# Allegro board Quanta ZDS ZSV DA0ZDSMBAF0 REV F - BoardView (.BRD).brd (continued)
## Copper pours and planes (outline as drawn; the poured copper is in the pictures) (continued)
VCCSA on IN1 (solid shape): 116.75,46.95 116.75,46.84 116.75,46.84 116.75,46.35 116.48,46.08 116.48,45.81 116.69,45.6 116.69,45.23 116.46,44.99 116.46,44.69 116.49,44.66 116.68,44.47 116.69,44.45 116.7,44.43 116.7,44.11 116.49,43.91 116.49,43.56 116.69,43.36 116.7,43.34 116.7,43.32 116.7,42.99 116.48,42.76 116.48,42.42 116.7,42.2 116.7,41.9 116.46,41.65 116.46,41.32 116.49,41.3 116.7,41.09 116.7,40.76 116.46,40.52 116.46,40.22 116.68,40 116.69,39.98 116.7,39.96 116.7,39.64 116.46,39.41 116.46,39.13 116.38,39.05 116.12,39.05 116.06,39.11 116.06,42.26 116.09,42.29 116.09,46.14 116.43,46.48 116.46,46.5 116.5,46.57 116.52,46.65 116.5,46.74 116.5,46.75 116.5,46.92 116.56,46.98 116.71,46.98
VCCSA on IN1 (solid shape): outline of 291 points within 136.75,46.1 153.19,56.74
VCCSA on GND1 (solid shape): 116.43,46.08 116.48,46.06 116.52,46.03 116.52,46 116.53,45.87 116.63,45.78 116.66,45.76 116.66,45.76 116.66,45.03 116.66,45.03 116.63,45.02 116.51,44.84 116.63,44.66 116.64,44.65 116.66,44.63 116.66,43.92 116.66,43.91 116.63,43.9 116.51,43.72 116.63,43.54 116.64,43.54 116.66,43.51 116.66,42.87 116.66,42.85 116.65,42.84 116.47,42.66 116.47,42.49 116.69,42.27 116.69,41.68 116.51,41.5 116.65,41.3 116.68,41.28 116.69,41.25 116.69,40.6 116.68,40.57 116.65,40.55 116.51,40.37 116.65,40.18 116.67,40.18 116.69,40.15 116.69,39.71 116.58,39.61 116.2,39.61 116.1,39.71 116.1,46 116.18,46.08
VCCSA on IN2 (solid shape): 153.79,56.05 153.79,48.57 153.47,48.25 149.79,48.25 147.66,50.38 147.62,50.38 147.62,50.46 147.65,50.48 149.36,53.25 147.82,56.13 147.77,56.24 147.87,56.32 153.53,56.32
VCCSA on IN2 (solid shape): 116.56,45.96 116.56,44.44 116.64,44.36 116.64,44.27 116.55,44.18 116.55,42.2 116.63,42.12 116.63,42.05 116.59,42.01 116.59,41.03 116.64,40.98 116.64,40.91 116.59,40.86 116.59,39.87 116.64,39.82 116.64,39.8 116.53,39.69 116.42,39.69 116.39,39.66 115.86,39.66 115.78,39.73 115.78,39.97 115.78,39.98 115.81,40.09 115.78,40.21 115.78,40.22 115.78,40.48 115.83,40.64 115.78,40.8 115.78,41.05 115.79,41.06 115.83,41.2 115.79,41.35 115.78,41.36 115.78,41.66 115.79,41.67 115.83,41.81 115.79,41.95 115.78,41.97 115.78,45.77 115.79,45.8 115.79,46.09 115.88,46.18 116.34,46.18
VCCSA on IN2 (solid shape): 142.83,55.65 142.83,51.1 142.46,50.73 141.91,50.73 140.49,52.15 140.47,52.26 140.57,52.32 141.33,54.08 139.57,53.32 139.51,53.22 139.4,53.24 136.63,56.01 136.6,56.13 136.7,56.19 142.29,56.19
VCCSA on SVCC (solid shape): 118.87,54.61 118.87,51.67 118.94,51.67 118.98,51.66 118.99,51.62 118.99,51.48 116.76,49.24 116.76,48.25 116.78,48.22 116.78,42.52 116.79,42.52 116.79,38.71 116.77,38.68 116.74,38.66 116.08,38.66 115.8,38.94 115.8,39.37 115.86,39.54 115.8,39.71 115.8,40.01 115.81,40.09 115.8,40.17 115.8,40.51 115.8,40.52 115.83,40.64 115.8,40.77 115.8,40.78 115.8,41.08 115.8,41.09 115.83,41.2 115.8,41.32 115.8,41.33 115.8,41.69 115.8,41.7 115.83,41.81 115.8,41.93 115.8,41.94 115.8,42.12 115.79,42.12 115.79,42.3 114.88,43.21 114.75,43.21 114.52,43.44 114.52,47.66 114.52,48.42 114.54,48.43 114.61,48.62 114.54,48.81 114.53,48.83 114.52,48.85 114.52,55.1 114.78,55.35 118.13,55.35
VCCSA on IN3 (solid shape): 116.81,46.05 116.81,39.91 116.74,39.83 116.28,39.83 116.17,39.94 116.17,43.22 116.1,43.29 116.1,45.8 116.45,46.15 116.71,46.15
VCCSA on IN3 (solid shape): 153.94,56.18 153.94,51.9 153.7,51.67 149.28,51.67 149.03,51.92 149.15,54.5 147.35,56.37 147.23,56.41 147.17,56.52 147.25,56.61 153.52,56.61
VCCSA on IN3 (solid shape): outline of 131 points within 136.82,51.7 145.03,56.61
VCCSA on GND2 (solid shape): 116.76,45.98 116.76,39.99 116.66,39.89 116.3,39.89 116.15,40.04 116.15,40.83 116.15,40.87 116.15,40.91 116.15,42.94 116.16,42.96 116.17,42.98 116.26,43.16 116.17,43.34 116.16,43.35 116.15,43.37 116.15,45.28 116.16,45.29 116.18,45.39 116.16,45.49 116.15,45.5 116.15,45.79 116.45,46.08 116.65,46.08
VCCSA on IN4 (solid shape): outline of 141 points within 115.32,40.19 117.7,54.3
VCCSA_DDR on BOTTOM (solid shape): 115.08,51.43 115.08,50.88 115.44,50.53 115.44,49.26 114.94,48.76 114.67,48.76 114.66,48.78 114.39,48.78 114.12,49.05 114.12,51.47 114.17,51.52 114.99,51.52
VCCSA_DDR on IN3 (solid shape): 115.69,49.51 115.69,48.75 115.56,48.62 114.93,48.62 114.8,48.75 114.8,49.64 114.93,49.77 115.44,49.77
VDDQ_SRC on TOP (solid shape): 79.19,59.71 79.19,54.75 79.37,54.57 79.37,54.08 79.27,54.08 79.27,52.6 79.09,52.42 78.07,52.42 77.92,52.57 77.92,54.12 77.31,54.73 75.74,54.73 75.33,55.13 75.33,59.35 75.79,59.81 79.09,59.81
VDDQ_SRC on BOTTOM (solid shape): 79.12,55.31 79.12,54.85 79,54.74 78.42,54.74 78.36,54.68 77.72,54.68 77.54,54.85 77.54,55.21 77.77,55.44 78.99,55.44
VDDQ_VIN on TOP (solid shape): 71.8,57.17 71.8,55.17 72.03,54.94 72.03,54.93 72.03,53.79 72.03,53.63 72.1,53.56 73.06,53.56 73.06,53.57 73.06,54.26 73.12,54.32 73.6,54.32 73.65,54.27 73.65,51.91 73.53,51.79 71.76,51.79 71.01,52.54 70.66,52.54 70.4,52.8 70.4,56.45 69.95,56.91 69.95,57.14 70.07,57.27 71.7,57.27
VINLDO1 on TOP (solid shape): 79.12,46.62 79.12,45.74 78.91,45.53 75.13,45.53 74.85,45.25 73.37,45.25 73.09,45.53 71.98,45.53 71.9,45.61 71.9,45.79 72,45.89 74.26,45.89 75.08,46.7 79.04,46.7
VINVR2 on TOP (solid shape): 70.15,42.81 70.15,42.09 70.14,42.07 70.12,42.04 70.11,42 70.11,41.15 70.11,41.15 70.11,40.86 70.12,40.81 70.14,40.75 70.15,40.74 70.15,40.66 70.27,40.53 70.63,40.53 71.14,40.02 71.17,40.02 72.28,38.9 72.28,38.55 72.18,38.45 70,38.45 69.86,38.59 69.86,39.42 69.39,39.89 69.39,40.86 69.78,41.25 69.78,41.73 69.87,41.81 69.87,42.79 69.94,42.87 70.1,42.87
13_CCD_PW on BOTTOM (solid shape): 4.11,18.85 4.11,17.89 4.23,17.77 6.38,17.77 6.48,17.67 6.48,16.81 6.34,16.67 2.79,16.67 2.56,16.9 2.56,19.12 2.64,19.2 3.76,19.2
8350_GND on IN3 (solid shape): 162.93,13.44 162.93,13.22 162.78,13.06 162.53,13.06 162.38,12.91 162.38,12.71 162.27,12.61 161.94,12.61 161.87,12.68 161.87,13.14 162.4,13.67 162.71,13.67
+1.8U on TOP (solid shape): 89.05,59.63 89.05,58.16 88.84,57.95 88.46,57.95 88.33,58.08 86.51,58.08 86.3,58.28 86.3,59.63 86.48,59.81 88.87,59.81
+1.8U on BOTTOM (solid shape): 131.74,17.54 131.74,17.53 131.85,17.43 132.89,17.43 133.09,17.23 133.09,14.87 132.94,14.72 129.71,14.72 129.15,15.28 129.15,16.33 129.24,16.56 129.15,16.79 129.15,17.13 129.24,17.36 129.15,17.59 129.15,17.85 129.23,17.92 131.36,17.92
+1.8U on BOTTOM (solid shape): 179.04,11.39 179.04,10.44 179.04,10.44 179.04,9.97 178.5,9.43 177.79,9.43 177.37,9.02 177.36,9.02 177.36,8.04 177.31,7.98 177.11,7.98 177.07,8 177.06,8.03 177.06,9.02 176.86,9.02 176.86,8.03 176.85,8 176.81,7.98 176.65,7.98 176.56,8.08 176.56,9.02 176.56,9.16 176.78,9.38 176.78,10.01 177.03,10.27 177.74,10.27 177.79,10.32 177.79,11.52 177.92,11.64 178.79,11.64
+1.8U on BOTTOM (solid shape): 147.95,14.49 148.14,14.43 148.34,14.49 148.74,14.49 148.93,14.43 149.12,14.49 149.55,14.49 149.74,14.43 149.94,14.49 150.34,14.49 150.41,14.46 150.43,14.44 150.44,14.41 150.44,11 150.22,10.78 148.91,10.78 148.69,11.01 148.69,12.22 148.58,12.33 147.67,12.33 147.52,12.48 147.52,14.34 147.67,14.49
+1.8U on BOTTOM (solid shape): 101.16,17.77 101.16,17.58 101.07,17.35 101.16,17.12 101.16,16.79 101.07,16.56 101.16,16.33 101.16,15.98 101.07,15.75 101.16,15.52 101.16,15.19 101.09,15.08 101.07,14.94 101.06,14.92 100.81,14.67 97.51,14.67 97.23,14.95 97.23,17.64 97.45,17.87 101.06,17.87
+1.8U on BOTTOM (solid shape): 155.77,43.11 155.77,42.12 155.67,42.02 153.08,42.02 152.42,42.68 151.89,42.68 151.84,42.69 151.79,42.68 150.78,42.68 150.74,42.68 150.39,42.32 150.39,42.15 150.26,42.02 149.29,42.02 149.27,42.03 149.25,42.04 148.96,42.21 148.68,42.04 148.66,42.03 148.63,42.02 148.51,42.02 148.49,42.03 148.47,42.05 148.18,42.22 147.88,42.05 147.87,42.03 147.84,42.02 147.62,42.02 147.49,42.15 147.49,43.19 147.59,43.29 155.59,43.29
+1.8U on BOTTOM (solid shape): outline of 223 points within 111.37,12.08 118.94,18.02
+1.8U on BOTTOM (solid shape): outline of 272 points within 147.16,24.72 155.65,32.29
+1.8U on IN3 (solid shape): 89.51,58.79 89.62,58.42 90,58.42 90.54,58.42 90.63,58.33 90.63,55.52 93.77,52.38 93.77,44.67 93.26,44.16 92.45,44.16 91.99,44.62 91.99,51.83 88.9,54.93 88.9,56.36 88.91,56.56 88.88,56.76 88.85,56.97 88.79,57.17 88.79,57.43 88.52,57.7 88.5,57.7 88.36,57.87 88.2,58.02 87.12,58.02 86.89,58.26 86.89,58.61 87.07,58.79
+1.8U on IN3 (solid shape): outline of 14479 points within 90.29,11.94 156.36,43.05
+1.8U on IN4 (solid shape): outline of 600 points within 85.99,24.62 95.24,45.61
+1.8U on IN4 (solid shape): outline of 1010 points within 153,10.45 179.27,18.86
+1.8U_S2 on TOP (solid shape): 86.02,59.5 86.02,58.33 85.89,58.19 85.66,58.19 84.86,57.39 83.82,57.39 83.79,57.41 83.77,57.44 83.77,58.12 83.57,58.12 83.57,57.44 83.56,57.41 83.52,57.39 83.46,57.39 83.4,57.46 83.4,58.34 84.07,59.01 84.07,59.2 84.2,59.32 84.7,59.32 85.03,59.65 85.87,59.65
+BAT_DIS on BOTTOM (solid shape): 82.52,21.1 82.52,18.43 81.68,17.6 81.68,16.72 81.71,16.7 81.71,15.31 81.49,15.09 80.58,15.09 80.46,15.2 80.46,15.99 80.23,16.22 78.56,16.22 78.46,16.32 78.46,18.13 77.54,19.04 77.49,19.27 77.31,19.43 77.31,21.2 77.52,21.4 82.21,21.4
+BATCHG on BOTTOM (solid shape): 86.41,18.76 86.41,13.93 86.15,13.68 84.61,13.68 84.61,13.73 83.06,13.73 82.87,13.91 82.87,15.84 83.15,16.12 83.28,16.12 83.33,16.17 83.33,16.65 83.36,16.68 83.36,18.71 83.59,18.94 86.23,18.94
+MUX_PWR on BOTTOM (solid shape): 240.15,22.59 240.15,21.44 240.91,20.68 240.91,18.9 240.4,18.4 239.64,18.4 239.39,18.65 239.39,22.33 239.77,22.71 240.02,22.71
+POA_PWR on BOTTOM (solid shape): 171.64,14.6 171.64,14.35 171.14,13.86 171.14,13.27 171.29,13.11 172.03,13.11 172.13,13.01 172.13,12.45 172,12.33 170.94,12.33 170.68,12.07 170.68,11.92 170.66,11.89 170.28,11.89 170.17,12 170.17,12.28 170.33,12.43 170.5,12.43 170.71,12.63 170.71,14.64 170.76,14.69 171.55,14.69
+PRWSRC on BOTTOM (solid shape): 88.29,23.81 88.29,22.95 88.77,22.47 88.77,21.55 89.05,21.28 89.73,21.28 89.82,21.19 89.82,19.54 89.15,18.86 86.89,18.86 86.61,19.14 86.61,19.83 86.69,19.91 86.69,20.59 86.68,20.59 86.68,21.13 86.19,21.62 86.19,23.77 86.47,24.04 88.05,24.04
+SMDDR_VREF_CA on BOTTOM (solid shape): 155.6,24.58 155.6,20.92 155.42,20.74 154.58,20.74 154.45,20.87 154.45,24.63 154.48,24.65 155.52,24.65
+SMDDR_VREF_DQA on BOTTOM (solid shape): 140.05,20.72 140.05,19.19 139.92,19.07 138.6,19.07 138.57,19.11 138.48,19.2 138.48,20.79 138.55,20.87 139.9,20.87
+SMDDR_VREF_DQA on BOTTOM (solid shape): 140.43,40.07 140.43,35.96 140.28,35.8 138.78,35.8 138.69,35.89 138.68,35.92 138.68,37.43 138.7,37.44 138.68,37.45 138.68,40.12 138.75,40.2 140.3,40.2
+SMDDR_VREF_DQA on IN3 (solid shape): 143.6,37.12 143.6,36.44 143.57,36.41 143.55,36.41 139.77,36.41 139.59,36.58 139.59,38.62 139.69,38.72 142.01,38.72
+SMDDR_VREF_DQA on IN3 (solid shape): 143.81,20.15 143.81,19.06 143.68,18.93 143.38,18.93 142.94,19.37 142.93,19.38 142.74,19.59 142.46,19.54 139.92,19.54 139.9,19.51 139.57,19.51 139.39,19.69 139.39,20.58 139.64,20.84 143.12,20.84
+SMDDR_VREF_DQB on BOTTOM (solid shape): 107.69,26.84 107.69,24.77 106.8,23.88 106.24,23.88 104.92,25.2 104.92,26.74 105.1,26.91 107.61,26.91
+SMDDR_VREF_DQB on BOTTOM (solid shape): 123.85,26.96 123.9,26.91 123.9,26.04 124.3,25.64 124.3,24.14 124.1,23.93 123.21,23.93 123.03,24.11 123.03,25.47 122.73,25.77 120.9,25.77 120.77,25.9 120.77,26.89 120.85,26.96 123.44,26.96
+SMDDR_VTERM on BOTTOM (solid shape): 138.35,39.05 138.35,38.39 138.22,38.26 136.98,38.26 136.85,38.39 136.85,38.83 137.14,39.12 138.27,39.12
+SMDDR_VTERM on BOTTOM (solid shape): 121.36,27.69 121.36,27.34 121.28,27.26 120.59,27.26 120.21,26.88 120.21,26.02 120.14,25.94 119.37,25.94 119.25,26.07 119.25,27.66 119.32,27.73 121.32,27.73
+SMDDR_VTERM on IN3 (solid shape): 121.08,26.14 121.08,25.84 121,25.76 119.25,25.76 119.17,25.84 119.17,26.19 119.27,26.3 120.92,26.3
+SMDDR_VTERM on IN3 (solid shape): 137.74,38.51 137.74,37.19 137.61,37.07 136.72,37.07 136.6,37.19 136.6,37.85 137.41,38.67 137.59,38.67
+SMDDR_VTERM on IN4 (solid shape): 120.95,26.19 120.95,25.86 120.87,25.79 118.74,25.79 118.66,25.86 118.66,26.25 118.71,26.3 120.85,26.3
+VA on TOP (solid shape): outline of 909 points within 201.67,2.52 215,22.08
+VA on BOTTOM (solid shape): 96.9,17.97 96.9,9.6 97.62,8.88 98.37,8.88 98.57,8.68 98.57,6.43 98.16,6.03 98.16,5.15 97.83,4.82 92.89,4.82 92.48,5.23 92.48,13.17 93.67,14.37 93.67,17.8 94.43,18.56 96.31,18.56
+VA on BOTTOM (solid shape): 210.18,21.44 211.45,21.44 211.7,21.19 211.7,20.3 212.21,19.79 212.21,16.66 212.06,16.52 212.06,15.7 212.21,15.56 212.21,13.95 212.46,13.7 212.46,12.55 212.34,12.43 208.78,12.43 208.65,12.55 208.65,13.32 208.53,13.44 206.5,13.44 206.11,13.82 206.11,22.08 206.37,22.33 209.29,22.33
+VA on IN4 (solid shape): outline of 6127 points within 95.52,2.49 206.5,10
+VAD on BOTTOM (solid shape): 71.65,17.29 71.65,15.97 71.34,15.66 70.71,15.66 70.06,16.31 70.06,16.46 70.05,16.47 70.05,17.31 70.24,17.5 71.43,17.5
+VAD on BOTTOM (solid shape): 94.15,22.42 94.15,18.61 93.42,17.87 93.42,14.49 93.14,14.21 88.92,14.21 88.51,14.62 88.51,18.4 88.64,18.53 89.48,18.53 90.11,19.17 90.11,22.21 90.57,22.67 90.57,23.54 90.83,23.79 92.78,23.79
+WL_VDD on TOP (solid shape): 40.93,57.46 40.93,55.44 40.85,55.36 39.65,55.36 39.55,55.47 39.55,57.48 39.65,57.59 40.8,57.59
+WL_VDD on TOP (solid shape): 194.71,39.81 194.71,35.49 194.41,35.19 190.7,35.19 190.65,35.24 190.65,36.1 191.15,36.61 191.15,38.59 192.58,40.01 194.51,40.01
+WL_VDD on TOP (solid shape): 199.55,34.46 199.89,34.25 200.23,34.44 200.44,34.44 200.88,34 202.53,34 202.64,33.9 202.64,33.7 201.12,33.7 201.12,33.5 202.61,33.5 202.64,33.47 202.64,33.24 202.59,33.19 198.37,33.19 198.04,32.85 197.49,32.85 197.29,33.05 197.29,33.82 197.93,34.46
+WL_VDD on TOP (solid shape): outline of 865 points within 94.25,48.15 202.64,59.97
+WL_VDD on BOTTOM (solid shape): outline of 775 points within 39.24,46.84 69.21,59.8
+WL_VDD on SVCC (solid shape): outline of 82 points within 65.65,53.19 99.43,59.97
+WL_VDD on SVCC (solid shape): outline of 153 points within 193.92,32.75 203.38,53.07
ADOGND on TOP (solid shape): outline of 1155 points within 236.69,2.04 266.07,14.03
ADOGND on BOTTOM (solid shape): 257.12,13.76 257.12,12.03 256.94,11.85 253.36,11.85 253.08,12.13 253.08,13.86 253.21,13.99 256.89,13.99
ADOGND on BOTTOM (solid shape): 241.29,4.84 241.29,4.49 241.19,4.38 238.88,4.38 238.81,4.46 238.81,4.85 238.84,4.89 239.48,4.89 239.56,4.97 241.17,4.97
ADOGND on BOTTOM (solid shape): 268.83,11.73 268.85,11.62 268.76,11.56 262.94,11.56 262.94,3.44 263.88,3.44 263.88,2.99 261.93,2.99 261.93,12.43 268.14,12.43
ADOGND on IN1 (solid shape): outline of 1062 points within 236.69,2.04 262.94,14.03
ADOGND on GND1 (solid shape): outline of 1125 points within 236.62,1.94 269.53,14.04
ADOGND on SGND (solid shape): 258.29,12.49 261.62,12.49 262.87,13.74 267.45,13.74 268.71,12.49 274.74,12.49 274.78,12.47 274.79,12.44 274.79,11.61 274.78,11.57 274.74,11.56 262.94,11.56 262.94,3.44 274.74,3.44 274.78,3.43 274.79,3.39 274.79,2.66 274.78,2.62 274.74,2.61 272.35,2.61 270.69,1.51 269.72,1.51 268.8,2.42 266.06,2.42 265.57,1.94 237.41,1.94 236.62,2.73 236.62,7.02 236.8,7.2 237.69,7.2 237.79,7.1 237.79,5.58 238.4,4.97 240.79,4.97 240.96,5.14 240.96,7.05 241.22,7.31 243.84,7.31 244.12,7.58 245.31,7.58 245.36,7.53 245.36,6.67 245.28,6.59 244.32,6.59 244.09,6.37 244.09,5.12 243.58,4.61 243.58,4.44 243.58,4.42 243.56,4.4 243.28,4.18 242.94,4.18 242.62,3.85 242.62,3.24 243.02,2.83 244.32,2.83 244.65,2.5 246.5,2.5 246.86,2.86 246.86,5.83 246.91,5.88 250.24,5.88 250.54,6.19 250.54,10.88 250.82,11.16 250.82,13.51 250.97,13.68 250.97,13.91 251.1,14.04 256.74,14.04
ADOGND on SVCC (solid shape): 258.29,12.49 261.37,12.49 261.62,12.49 262.87,13.74 267.46,13.74 267.89,13.31 267.89,13.19 267.78,13.08 264.42,13.08 264.3,13.08 263.3,13.07 262.85,12.97 262.56,12.86 262.29,12.7 261.99,12.44 261.93,12.4 261.71,12.11 261.58,11.85 261.47,11.54 261.42,11.16 261.42,2.57 260.88,2.03 237.32,2.03 236.62,2.73 236.62,7.02 236.8,7.2 237.69,7.2 237.79,7.1 237.79,5.58 238.4,4.97 240.79,4.97 240.96,5.14 240.96,7.05 241.22,7.31 243.84,7.31 244.12,7.58 245.31,7.58 245.36,7.53 245.36,6.67 245.28,6.59 244.32,6.59 244.09,6.37 244.09,5.12 243.58,4.61 243.58,4.44 243.58,4.42 243.56,4.4 243.28,4.18 242.94,4.18 242.62,3.85 242.62,3.24 243.02,2.83 244.32,2.83 244.65,2.5 246.5,2.5 246.86,2.86 246.86,5.83 246.91,5.88 250.24,5.88 250.54,6.19 250.54,10.88 250.82,11.16 250.82,13.51 250.97,13.68 250.97,13.91 251.1,14.04 256.74,14.04
ADOGND on GND2 (solid shape): outline of 1125 points within 236.62,1.94 269.53,14.04
ADOGND on IN4 (solid shape): outline of 1098 points within 236.69,2.04 262.92,14.03
BATDIS_G on BOTTOM (solid shape): 90.42,23.92 90.42,22.95 89.96,22.49 89.96,21.73 89.68,21.45 89.1,21.45 89.05,21.5 89.05,22.34 88.56,22.82 88.56,24.04 88.59,24.07 90.27,24.07
BATT+ on BOTTOM (solid shape): 87.68,12.29 87.68,9.86 87.44,9.63 81.84,9.63 81.69,9.77 81.69,12.62 81.89,12.82 82.7,12.82 83.28,13.4 86.57,13.4
BQB_1 on BOTTOM (solid shape): 72.69,22.65 72.69,21.33 72.56,21.2 72.05,21.2 71.83,21.43 71.83,22.22 71.84,22.22 71.84,22.69 72.03,22.88 72.46,22.88
BQBATDRV on BOTTOM (solid shape): 82.09,14.94 82.09,14.59 81.63,14.14 80.67,14.14 80.46,14.34 80.46,14.67 80.74,14.95 81.5,14.95 81.55,14.99 82.04,14.99
BQHIDRV on BOTTOM (solid shape): 77.06,20.26 77.06,19.51 77.36,19.21 77.36,18.96 77.29,18.88 76.83,18.88 76.55,19.16 76.55,19.83 76.37,20.01 76.25,20.01 75.99,20.26 75.99,20.64 76.04,20.69 76.63,20.69
BQLODRV on BOTTOM (solid shape): 70.33,24.87 70.33,24.14 70.07,23.88 70.07,23.61 69.54,23.08 69.34,23.08 69.24,23.18 69.24,23.28 69.36,23.41 69.36,24.85 69.51,25 70.2,25
BQPHASE on BOTTOM (solid shape): 71.61,21.8 71.61,21.01 71.47,20.87 70.4,20.87 70.15,21.12 69.77,21.12 69.74,21.15 69.74,21.35 69.77,21.38 70.89,21.38 71.09,21.58 71.09,21.76 71.17,21.83 71.57,21.83
BQPHASE on BOTTOM (solid shape): 81.83,25.75 81.83,21.96 81.45,21.58 73.78,21.58 73.55,21.35 73.25,21.35 73.02,21.58 73.02,22.32 73.4,22.7 76.98,22.7 77.13,22.85 77.13,24.35 77.52,24.73 79.27,24.73 79.47,24.93 79.47,25.97 79.62,26.13 81.45,26.13
BQVCC on BOTTOM (solid shape): 69.51,20.61 70.89,20.61 71.04,20.46 71.04,19.83 71.55,19.32 71.55,18.51 71.37,18.33 70.23,18.33 68.14,20.41 68.14,20.84 68.27,20.97 69.16,20.97
BST_CORE on BOTTOM (solid shape): 182.98,29.99 182.98,28.69 181.43,27.14 180.51,27.14 180.45,27.21 180.45,27.55 180.53,27.63 180.79,27.63 182.06,28.9 182.06,30.01 182.14,30.09 182.87,30.09
BST_GT1 on BOTTOM (solid shape): 174.29,30.01 174.29,28.56 175.23,27.63 175.69,27.63 175.76,27.55 175.76,27.22 175.69,27.14 174.98,27.14 173.43,28.69 173.43,30.04 173.48,30.09 174.21,30.09
DRVHVR1 on TOP (solid shape): 66.75,42.89 66.75,42.64 66.64,42.53 66.42,42.53 65.83,41.95 65.83,36.03 64.66,34.86 61.43,34.86 61,35.29 61,36.81 61.16,36.96 61.49,36.96 61.59,36.86 61.59,35.8 61.64,35.75 61.65,35.75 61.84,35.55 64.26,35.55 64.99,36.29 64.99,38.88 65.21,39.09 65.21,42.04 66.14,42.97 66.67,42.97
DRVHVR3 on TOP (solid shape): 75.33,40.4 76.45,40.4 76.55,40.3 76.55,39.87 75.1,39.87 73.1,41.87 73.1,42.18 72.69,42.59 72.44,42.59 72.38,42.64 72.38,42.92 72.41,42.94 72.79,42.94
DRVHVR4 on TOP (solid shape): 73.65,51.52 73.65,48.4 72.87,47.61 72.46,47.61 72.38,47.69 72.38,47.87 72.46,47.95 72.61,47.95 72.99,48.33 72.99,51.53 73.11,51.64 73.53,51.64
DRVHVR5 on TOP (solid shape): 67.15,49.27 67.15,48.63 67.15,48.59 67.15,48.17 67.07,48.1 66.95,48.1 66.87,48.17 66.87,48.53 65.69,49.71 62.69,49.71 62.58,49.82 62.58,50.21 62.59,50.21 62.59,50.38 62.69,50.48 65.93,50.48
DRVLVR1 on TOP (solid shape): 66.68,44.32 66.68,44.22 66.41,43.95 66.17,43.95 65.84,43.61 64.78,43.61 62.69,41.52 61.91,41.52 61.6,41.21 61.6,39.26 61.58,39.25 61.05,39.25 60.97,39.33 60.97,41.53 61.63,42.2 62.2,42.2 62.2,42.2 62.44,42.2 63.3,43.06 63.3,43.3 64.35,44.34 65.86,44.34 65.94,44.43 66.57,44.43
DRVLVR3 on TOP (solid shape): 73.31,44.47 73.71,44.47 74.87,43.3 76.45,43.3 76.55,43.2 76.55,42.75 76.47,42.67 74.43,42.67 73.08,44.03 73.09,44.06 73.01,44.3 72.76,44.23 72.76,44.22 72.67,44.14 72.44,44.14 72.38,44.19 72.38,44.39 72.46,44.47 72.71,44.47 72.85,44.6 73.17,44.6
DRVLVR4 on TOP (solid shape): 77.41,53.74 77.41,48 76.31,46.89 75.04,46.89 74.16,46.01 72.38,46.01 72.31,46.09 72.31,46.34 72.38,46.42 73.45,46.42 74.76,47.73 74.77,47.72 75.89,47.72 76.68,48.5 76.68,53.28 76.12,53.83 75.21,53.83 75.11,53.93 75.11,54.38 75.22,54.49 76.66,54.49
DRVLVR5 on TOP (solid shape): 65.6,47.31 65.82,47.31 66,47.13 66.06,47.02 66.17,46.97 66.18,46.96 66.59,46.96 66.7,46.85 66.7,46.65 66.64,46.6 65.68,46.6 65.5,46.78 62.71,46.78 62.61,46.88 62.61,47.35 62.68,47.43 65.48,47.43
HG_CORE on BOTTOM (solid shape): 181.68,29.99 181.68,28.9 180.79,28.01 180.72,28.01 180.59,28.13 180.59,28.31 180.72,28.44 180.72,29.94 180.89,30.11 181.55,30.11
HG_CORE_L on TOP (solid shape): 187.17,36.16 187.17,34.32 187.01,34.17 186.4,34.17 186.28,34.3 186.28,36.24 186.38,36.34 186.99,36.34
HG_CORE_L on BOTTOM (solid shape): 181.6,31.84 181.6,30.6 181.4,30.39 180.82,30.39 180.66,30.55 180.66,31.92 180.77,32.02 181.43,32.02
HG_GT1 on BOTTOM (solid shape): 175.69,29.99 175.69,28.13 175.56,28.01 175.38,28.01 174.85,28.54 174.85,30.04 174.95,30.14 175.53,30.14
HG_GT1_L on TOP (solid shape): 171.64,40.39 171.64,40.04 171.55,39.94 171.19,39.94 170.91,39.66 170.91,39.36 170.66,39.11 169.67,39.11 169.49,39.28 169.49,40.4 169.61,40.52 171.51,40.52
HG_GT1_L on BOTTOM (solid shape): 176.56,31.85 176.56,31.72 175.79,30.95 175.79,30.52 175.64,30.37 174.98,30.37 174.77,30.57 174.77,31.84 174.92,31.99 176.41,31.99
HG_SA on BOTTOM (solid shape): 162.52,53.51 162.52,49.74 161.61,48.83 158.98,48.83 158.89,48.93 158.89,49.8 158.98,49.9 161.18,49.9 161.7,50.42 161.7,52.76 161.36,53.1 158.36,53.1 158.03,53.42 158.03,54.01 158.34,54.31 161.71,54.31
HG_SA_L on TOP (solid shape): 156.59,49.48 156.59,49.04 156.78,48.85 157.21,48.85 157.26,48.81 157.26,48.19 157.19,48.12 156.18,48.12 155.95,48.35 155.95,49.47 156.06,49.58 156.49,49.58
HG_SA_L on BOTTOM (solid shape): 158.62,49.78 158.62,49.06 158.55,48.99 156.06,48.99 155.95,49.1 155.95,49.74 156.04,49.84 158.56,49.84
L_SPK+ on TOP (solid shape): 89.99,6.94 89.99,6.66 89.83,6.51 89.83,5.32 89.71,5.19 88.79,5.19 88.69,5.29 88.69,6.56 89.38,7.25 89.68,7.25
L_SPK+ on TOP (solid shape): 10.81,4.55 10.81,4.43 10.38,4 10.38,3.21 10.1,2.93 9.39,2.93 9.09,3.23 9.09,3.8 10.19,4.91 10.46,4.91
L_SPK+ on BOTTOM (solid shape): 10.38,4.81 10.38,3.21 10.1,2.93 9.57,2.93 8.33,4.17 6.47,4.17 6.47,4.93 10.26,4.93
L_SPK+ on BOTTOM (solid shape): 245.33,8.35 245.33,8.19 245.31,8.17 244.35,8.17 244.35,8.17 243.5,8.17 243.05,7.71 242.77,7.71 242.72,7.76 242.72,8.07 243.02,8.37 245.31,8.37
L_SPK+ on IN2 (solid shape): 90.52,5.93 90.52,5.34 90.37,5.19 88.77,5.19 88.64,5.32 88.64,6.2 88.77,6.33 90.11,6.33
L_SPK+ on IN2 (solid shape): 233.9,9.53 233.9,9.38 234.41,8.87 234.41,8.52 234.28,8.39 233.42,8.39 233.12,8.69 233.12,9.81 233.17,9.86 233.57,9.86
L_SPK- on TOP (solid shape): 10.87,6.69 10.87,6.13 10.74,6 9.42,6 8.91,6.51 8.91,6.79 9.52,7.4 10.15,7.4
L_SPK- on TOP (solid shape): 91.94,5.11 91.94,4.17 91.81,4.05 90.62,4.05 90.62,5.16 90.19,5.6 90.19,6.23 90.24,6.28 90.77,6.28
L_SPK- on BOTTOM (solid shape): 10.38,6.84 10.38,5.52 10.28,5.42 6.47,5.42 6.47,6.18 8.3,6.18 9.49,7.37 9.85,7.37
L_SPK- on BOTTOM (solid shape): 242.64,8.78 244.35,8.78 244.35,8.77 245.31,8.77 245.33,8.75 245.33,8.6 245.31,8.58 242.92,8.58 242.79,8.45 242.26,8.45 242.16,8.55 242.16,8.91 242.21,8.96 242.46,8.96
L_SPK- on IN2 (solid shape): 92.32,4.22 92.32,3.72 92.2,3.59 91.23,3.59 90.62,4.2 90.62,4.86 90.88,5.11 91.43,5.11
L_SPK- on IN2 (solid shape): 232.81,9.23 232.81,8.47 232.63,8.29 232.4,8.29 231.67,9.02 231.11,9.02 231.11,9.79 232.25,9.79
LDO3V on TOP (solid shape): 67.13,42.41 67.13,41.59 66.97,41.44 66.97,38.98 66.9,38.9 66.73,38.9 66.72,38.91 66.51,38.94 66.3,38.9 66.29,38.9 66.19,39.01 66.19,41.6 66.72,42.13 66.72,42.38 66.77,42.43 67.1,42.43
LDO3V on TOP (solid shape): 62.02,45.04 63.37,45.04 63.37,45.05 63.4,45.08 64.32,45.08 64.48,44.92 66.59,44.92 66.69,44.82 66.69,44.62 66.62,44.54 63.95,44.54 63.67,44.26 63.65,44.26 63.01,43.63 61.81,43.63 61.16,44.29 61.16,44.58 61.2,44.66 61.29,44.68 61.59,44.7 61.79,44.92 61.8,44.93 61.95,45.08 61.98,45.08
LDO3V on TOP (solid shape): 69.21,51.27 69.21,50.82 69.44,50.58 70.36,50.58 71.14,49.8 71.14,48.76 71.13,48.74 71.12,48.72 71.05,48.58 71.12,48.44 71.13,48.43 71.14,48.41 71.14,48.17 71.06,48.1 70.43,48.1 70.4,48.12 70.4,48.42 70.41,48.46 70.41,48.48 70.41,48.71 70.4,48.72 70.4,48.86 69.97,49.29 69.72,49.29 68.65,50.36 68.65,51.27 68.7,51.32 69.16,51.32
LDO3V on IN1 (solid shape): outline of 1327 points within 61.69,40.66 69.74,51.93
LDO5V on TOP (solid shape): 70.66,42.3 70.66,41.8 72.81,39.64 72.81,39.36 72.8,39.33 72.76,39.31 72.61,39.31 72.49,39.29 72.38,39.24 72.37,39.23 72.31,39.23 70.66,40.88 70.66,40.89 70.65,40.96 70.62,41.03 70.38,41.28 70.38,42.27 70.48,42.37 70.58,42.37
LDO5V on TOP (solid shape): 65.5,45.38 65.68,45.38 65.74,45.37 65.79,45.38 65.81,45.38 65.81,45.37 66.63,45.37 66.67,45.33 66.67,45.2 66.65,45.17 66.61,45.12 66.59,45.07 64.61,45.07 64.36,45.32 63.42,45.32 63.39,45.34 63.37,45.37 63.37,45.83 63.46,45.92 63.77,45.92 63.78,45.92 63.87,45.92 64.03,46.08 64.05,46.08 64.17,46.12 64.3,46.21 64.32,46.21 64.67,46.21
LDO5V on IN2 (solid shape): 72.97,39.69 74.06,39.69 74.11,39.64 74.11,39.46 74.1,39.43 74.06,39.41 72.21,39.41 71.95,39.66 71.95,39.94 71.97,39.97 72,39.99 72.67,39.99
LG_CORE on TOP (solid shape): 181.2,36.29 181.2,36.08 181.81,35.47 181.81,35.17 181.48,34.84 180.92,34.84 180.56,35.19 180.56,36.26 180.69,36.39 181.1,36.39
LG_CORE on BOTTOM (solid shape): 180.18,29.61 180.18,29.15 179.55,28.51 179.55,28.06 179.45,27.96 179.32,27.96 179.14,28.13 179.14,28.92 179.43,29.21 179.43,29.59 179.55,29.71 180.08,29.71
LG_GT1 on TOP (solid shape): 176.58,40.58 176.58,39.33 176.5,39.26 176.02,39.26 175.86,39.41 175.86,40.55 176.04,40.73 176.42,40.73
LG_GT1 on BOTTOM (solid shape): 176.73,29.66 176.73,29.45 177.26,28.92 177.26,28.74 177.05,28.53 177.05,28.02 177.01,27.98 176.8,27.98 176.78,28.01 176.78,28.72 176.17,29.33 176.17,29.71 176.25,29.78 176.6,29.78
LG_SA on TOP (solid shape): 156.46,53.63 156.46,52.73 157.03,52.16 157.03,51.84 157.25,51.63 157.25,51.2 157.18,51.13 156.74,51.13 156.29,51.58 156.29,52.11 155.89,52.51 155.89,53.59 155.95,53.64 156.44,53.64
NB681_VIN_PRIM on BOTTOM (solid shape): 162.01,25.97 162.01,24.38 162.93,23.46 162.93,23.17 163.55,22.55 163.55,21.6 163.38,21.42 161.72,21.42 161.56,21.27 161.56,20.96 161.08,20.48 160.65,20.48 160.5,20.63 160.5,22.11 161.07,22.68 161.07,23.8 161.7,24.43 161.7,26.01 161.75,26.06 161.92,26.06
NB681_VIN_VCCIO on TOP (solid shape): 56.48,46.87 56.48,46.16 56.92,45.73 56.92,45.68 56.92,45.67 56.92,44.77 56.97,44.72 56.97,44.55 56.69,44.28 56.69,44.01 56.45,43.77 55.36,43.77 55.16,43.57 55.16,42.37 55.09,42.3 54.93,42.3 54.88,42.35 54.88,43.59 54.53,43.95 54.53,46.9 54.63,47 56.36,47
NB681BST_PRIM on BOTTOM (solid shape): 163.87,28.02 163.87,27.68 163.43,27.24 162.16,27.24 162.01,27.09 162.01,26.47 161.94,26.4 161.78,26.4 161.75,26.43 161.75,27.47 162.39,28.12 163.78,28.12
NB681BST_VCCIO on TOP (solid shape): 55.14,41.94 55.14,41.43 55.29,41.28 55.75,41.28 55.98,41.05 55.98,40.8 55.87,40.7 55.37,40.7 54.93,41.13 54.93,41.94 54.98,41.99 55.09,41.99
NB681BST_VCCIO on BOTTOM (solid shape): 56.89,41.38 56.89,40.65 56.76,40.52 55.47,40.52 55.21,40.77 55.21,42.17 55.44,42.4 55.87,42.4
NB681SW_PRIM on BOTTOM (solid shape): 163.49,30.48 163.49,28.59 163.32,28.42 162.33,28.42 161.5,27.59 161.5,27.13 161.49,27.13 161.49,26.42 161.5,26.42 161.5,25.69 161.44,25.63 161.29,25.63 161.22,25.71 161.22,26.41 161.23,27.13 161.22,27.15 161.22,27.45 160.96,27.71 159.92,27.71 159.51,28.11 159.51,29.78 159.8,30.07 161.93,30.07 162.49,30.63 163.35,30.63
NB681SW_VCCIO on TOP (solid shape): 54.64,42.72 54.64,41.21 54.65,41.2 54.65,41.05 55.49,40.22 55.49,37.7 55.37,37.57 54.22,37.57 53.71,38.08 53.71,40.24 54.38,40.9 54.38,41.21 54.38,41.21 54.38,42.71 54.45,42.78 54.58,42.78
NB681SW_VCCIO on BOTTOM (solid shape): 54.65,40.65 54.65,40.16 54.5,40.01 54.5,38.92 54.35,38.77 52.04,38.77 51.96,38.84 51.96,39.86 52.19,40.09 53.28,40.09 53.97,40.77 54.53,40.77
NBSWON#_14_13 on BOTTOM (solid shape): 8.12,15.93 8.12,14.79 7.94,14.61 5.05,14.61 5.05,15.25 5.89,16.09 7.97,16.09
NBSWON#_14_13 on BOTTOM (solid shape): 42.92,9.38 42.92,7.97 42.79,7.84 41.04,7.84 40.96,7.91 40.96,9.43 41.04,9.51 42.79,9.51
NBSWON#_14_13 on IN2 (solid shape): outline of 291 points within 5.76,8.06 43.12,17
R_SPK+ on BOTTOM (solid shape): 244.09,9.57 245.31,9.57 245.33,9.54 245.33,9.44 245.32,9.4 245.28,9.39 243.45,9.39 243.33,9.51 243.33,9.87 243.38,9.92 243.73,9.92
R_SPK+ on IN3 (solid shape): 216.3,6.33 216.3,4.96 216.2,4.86 215.67,4.86 215.54,4.99 215.54,6.38 215.56,6.41 216.22,6.41
R_SPK- on BOTTOM (solid shape): 243.43,9.18 244.35,9.18 244.35,9.17 245.32,9.17 245.33,9.16 245.33,9.03 245.32,9 245.28,8.98 242.72,8.98 242.59,9.12 242.59,9.46 242.69,9.57 243.05,9.57
R_SPK- on IN3 (solid shape): 217.27,5.24 217.27,3.66 217.19,3.59 216.58,3.59 216.57,3.6 216.41,3.6 216.37,3.63 216.37,4.53 216.5,4.66 216.5,5.27 216.53,5.29 217.21,5.29
REGN6V on BOTTOM (solid shape): 72.05,23.97 72.05,23.36 71.9,23.21 71.14,23.21 71.06,23.13 70.43,23.13 70.1,22.8 69.97,22.8 69.82,22.95 69.82,23.08 70.86,24.12 71.9,24.12
RING2 on BOTTOM (solid shape): 258.21,10.66 258.21,9.54 258.11,9.44 256.59,9.44 256.48,9.54 256.48,10.66 256.56,10.73 258.13,10.73
RING2 on IN2 (solid shape): 258.24,10.56 258.24,9.44 258.11,9.31 252.04,9.31 251.76,9.59 251.76,10.33 252.17,10.73 258.06,10.73
RING2_R on BOTTOM (solid shape): 261.26,11.39 261.26,10.33 261.13,10.2 258.57,10.2 258.49,10.28 258.49,11.39 258.69,11.6 261.06,11.6
RING2_R on IN3 (solid shape): 261.26,11.37 261.26,10.43 261.11,10.28 259.05,10.28 259,10.33 259,11.42 259.1,11.52 261.11,11.52
RING2_R on IN3 (solid shape): 272.54,12.99 274.52,12.99 274.65,12.86 274.65,11.66 274.57,11.57 272.27,11.57 272.03,11.82 272.03,12.25 271.6,12.68 270,12.68 269.89,12.78 269.89,13.7 271.82,13.7
SLEEVE on BOTTOM (solid shape): 258.21,8.37 258.21,7.15 258.08,7.03 256.59,7.03 256.46,7.15 256.46,8.37 256.53,8.45 258.13,8.45
SLEEVE on IN2 (solid shape): 258.21,8.73 258.21,7.23 258.11,7.13 254.27,7.13 253.46,7.94 251.89,7.94 251.78,8.04 251.78,8.93 251.86,9.01 257.93,9.01
SLEEVE_R on BOTTOM (solid shape): 258.79,9.26 258.92,9.2 259.07,9.18 259.09,9.18 259.16,9.11 261.21,9.11 261.39,8.93 261.39,8.02 261.26,7.89 261.03,7.89 260.9,7.91 260.77,7.89 260.12,7.89 260.09,7.91 259.07,7.91 259,7.91 258.91,7.89 258.57,7.89 258.54,7.91 258.54,9.16 258.65,9.27 258.77,9.27
SLEEVE_R on IN1 (solid shape): 261.16,8.93 261.16,7.31 261.01,7.15 259.66,7.15 259.53,7.28 259.53,9.01 259.63,9.11 260.98,9.11
SLEEVE_R on IN2 (solid shape): 261.16,8.93 261.16,7.31 261.01,7.15 259.66,7.15 259.53,7.28 259.53,9.01 259.63,9.11 260.98,9.11
SM_VREF_CA on BOTTOM (solid shape): 157.12,26.96 157.12,26.35 156.92,26.14 156.71,26.14 156.51,26.35 155.8,26.35 155.7,26.25 155.7,26.14 155.7,26.14 155.7,24.96 155.62,24.88 154.63,24.88 154.55,24.96 154.55,26.79 154.66,26.89 154.71,26.89 154.98,27.16 156.92,27.16
SM_VREF_DQ0 on BOTTOM (solid shape): 138.5,40.17 138.5,39.61 138.44,39.56 137.03,39.56 136.89,39.41 136.58,39.41 136.44,39.54 136.44,40.17 136.52,40.25 138.42,40.25
SM_VREF_DQ1 on BOTTOM (solid shape): 125.5,27.03 126.22,27.03 126.36,26.89 126.36,26.09 126.2,25.94 124.28,25.94 124.15,26.08 124.15,26.93 124.23,27.01 124.78,27.01 124.81,27.03 125.5,27.03
SM_VREF_DQ1 on IN3 (solid shape): 125.47,27.29 125.47,26.17 125.39,26.09 124.56,26.09 124.48,26.17 124.48,27.34 124.5,27.36 125.39,27.36
SW_CORE on TOP (solid shape): 183.69,47.77 183.69,45.33 183.23,44.87 181.63,44.87 181.55,44.8 181.55,44.03 181.78,43.8 183.31,43.8 183.48,43.63 183.48,42.1 184.31,41.28 184.31,35.59 183.97,35.25 182.44,35.25 181.36,36.32 181.36,40.44 180.77,41.04 179.14,41.04 178.73,41.44 178.73,47.92 178.86,48.05 183.41,48.05
SW_CORE on BOTTOM (solid shape): 183.79,40.4 183.79,39 183.61,38.83 182.77,38.83 182.47,39.13 182.47,40.73 182.62,40.88 183.31,40.88
SW_CORE on BOTTOM (solid shape): 183.06,31.81 183.15,31.81 183.33,31.63 183.71,31.63 183.92,31.43 183.92,30.92 183.84,30.84 183.43,30.84 183.08,30.49 183.08,30.47 182.95,30.34 182.27,30.34 182.09,30.52 182.09,31.82 182.24,31.97 182.9,31.97
SW_GT1 on TOP (solid shape): 178.05,47.56 178.05,41.67 177.44,41.06 176.12,41.06 175.58,40.53 175.58,35.75 175.08,35.25 172.89,35.25 172.69,35.45 172.69,41.14 173.86,42.31 173.86,43.55 174.16,43.86 175.34,43.86 175.38,43.9 175.38,44.74 175.39,44.74 175.33,44.8 174.25,44.8 174,45.05 174,47.68 174.37,48.05 177.57,48.05
SW_GT1 on BOTTOM (solid shape): 174.31,31.89 174.31,30.62 174.11,30.42 173.5,30.42 173.38,30.55 173.38,31.79 173.63,32.04 174.16,32.04
SW_GT1 on BOTTOM (solid shape): 173.6,40.48 173.6,39.06 173.43,38.88 172.59,38.88 172.17,38.46 171.11,38.46 171.01,38.56 171.01,39.4 171.42,39.81 171.67,39.94 171.8,40.19 172.24,40.63 173.45,40.63
SW_SA on TOP (solid shape): 157.46,53.61 157.46,53.09 157.6,52.95 158.48,52.95 159.03,53.5 160.88,53.5 161.79,52.59 161.79,51.07 160.52,49.8 156.14,49.8 155.67,49.33 155.67,48.28 155.47,48.07 153.72,48.07 153.59,48.2 153.59,49.93 153.79,50.13 154.15,50.13 154.2,50.18 154.2,50.69 153.97,50.92 153.33,50.92 153.16,51.09 153.16,52.59 153.36,52.8 155.16,52.8 156.03,51.93 156.03,51.35 156.43,50.94 159.99,50.94 160.3,51.25 160.3,52.28 160.14,52.44 157.31,52.44 157.16,52.59 157.16,53.61 157.18,53.63 157.44,53.63
SW_SA on BOTTOM (solid shape): 161.21,52.49 161.21,50.71 160.85,50.36 159.01,50.36 158.86,50.5 158.86,51.35 158.96,51.45 160.42,51.45 160.57,51.6 160.57,51.86 160.19,52.24 160.19,52.64 160.45,52.9 160.8,52.9
SWVR1 on TOP (solid shape): 66.72,43.4 66.72,43.09 66.67,43.04 65.93,43.04 64.94,42.05 64.94,39.23 63.82,38.12 56.12,38.12 55.95,38.29 55.95,40.67 56.53,41.26 57.45,41.26 58.93,41.26 59.46,41.26 59.76,40.95 59.76,39.76 60.5,39.02 63.61,39.02 64.13,39.54 64.13,42.28 65.34,43.5 66.62,43.5
SWVR1 on BOTTOM (solid shape): 59.58,42.38 59.58,40.53 59.38,40.33 57.29,40.33 57.04,40.57 57.04,41.56 57.72,42.24 58.52,42.24 58.79,42.51 59.46,42.51
SWVR3 on TOP (solid shape): 84.12,44.47 84.12,40.96 83.59,40.43 80.44,40.43 79.52,41.34 74.65,41.34 72.94,43.04 72.44,43.04 72.38,43.09 72.38,43.29 72.47,43.37 73.3,43.37 74.24,42.43 79.01,42.43 79.55,42.97 79.55,44.47 79.83,44.74 83.84,44.74
SWVR3 on BOTTOM (solid shape): 81.17,41.9 81.17,41.11 80.89,40.83 79.04,40.83 78.86,41.01 78.86,41.87 79.06,42.08 81,42.08
SWVR4 on TOP (solid shape): 74.85,58.71 74.85,48.1 73.86,47.11 72.49,47.11 72.41,47.18 72.41,47.46 72.46,47.51 73.05,47.51 73.88,48.35 73.88,54.35 73,55.23 72.32,55.23 72.22,55.13 72.13,55.13 72.03,55.23 72.03,58.69 72.21,58.87 74.7,58.87
SWVR4 on BOTTOM (solid shape): 75.86,56.89 75.86,55.51 75.66,55.31 74.72,55.31 74.39,54.98 73.86,54.98 73.6,55.23 73.6,56.78 73.96,57.14 75.61,57.14
SWVR5 on TOP (solid shape): 57.4,55.94 57.4,50.79 59.37,48.82 61.3,48.82 61.31,48.83 63.02,48.83 63.26,48.58 65.76,48.58 66.36,47.97 66.52,47.97 66.64,47.84 66.64,47.64 66.54,47.53 65.85,47.53 65.73,47.65 60.42,47.65 59.76,47 56.71,47 54.02,49.69 52.44,49.69 52.09,50.05 52.09,53.68 54.83,56.42 56.92,56.42
SWVR5 on BOTTOM (solid shape): 60.73,49.41 60.73,48.85 61.13,48.45 61.69,48.45 61.87,48.27 61.87,47.35 61.72,47.2 59.96,47.2 59.84,47.33 59.84,49.41 59.96,49.54 60.6,49.54
TYPEC1_CCG1_CC2 on TOP (solid shape): 261.87,28.76 261.87,28.25 261.74,28.13 261.55,28.13 261.15,28.48 260.99,27.97 260.99,27.32 260.81,27.14 260.43,27.14 260.36,27.22 260.36,28.39 260.85,28.89 261.74,28.89
TYPEC1_USB0 on TOP (solid shape): 269.41,35.01 269.41,34.65 269.28,34.53 268.9,34.53 268.85,34.58 267.3,34.58 267.18,34.7 267.18,34.78 267.3,34.91 268.7,34.91 268.95,35.16 269.26,35.16
TYPEC1_USB0 on TOP (solid shape): 269.42,32.3 269.42,31.92 269.31,31.81 268.72,31.81 268.43,32.1 267.32,32.1 267.23,32.19 267.23,32.31 267.32,32.4 268.79,32.4 268.87,32.48 269.25,32.48
TYPEC1_USB0 on TOP (solid shape): 264.15,37.57 265.91,37.57 266.18,37.31 266.18,35.92 265.3,35.03 264.92,35.03 264.91,35.03 263.78,35.03 263.47,35.34 261.72,35.34 261.41,35.03 259.23,35.03 259.08,35.17 259.08,36.04 258.18,36.94 258.18,37.83 258.31,37.95 263.77,37.95
TYPEC1_USB0 on BOTTOM (solid shape): 203.32,30.46 203.57,30.43 203.81,30.46 203.95,30.46 205.83,28.58 210.93,28.58 211.07,28.44 211.07,26.13 210.98,26.04 206.68,26.04 206.44,25.8 206.44,24.95 205.46,23.98 204.56,23.98 203.78,24.76 203.78,27.73 203.26,28.25 203.26,29.11 202.9,29.47 201.07,29.47 200.92,29.62 200.92,30.37 201.01,30.46
TYPEC1_USB0 on IN2 (solid shape): outline of 4708 points within 202.56,17.17 269.47,37.38
TYPEC1_USB0_R on BOTTOM (solid shape): 201.95,27.73 203.23,27.73 203.43,27.53 203.43,25.25 203.36,25.19 202.31,25.19 201.3,26.2 198.48,26.2 198.35,26.32 198.35,28.72 198.51,28.88 200.8,28.88
TYPEC2_USB0 on TOP (solid shape): 269.44,18.3 269.44,17.91 269.33,17.81 268.73,17.81 268.45,18.1 267.34,18.1 267.25,18.19 267.25,18.31 267.34,18.4 268.81,18.4 268.89,18.47 269.26,18.47
TYPEC2_USB0 on TOP (solid shape): 269.43,21.01 269.43,20.65 269.3,20.52 268.92,20.52 268.85,20.6 267.3,20.6 267.2,20.7 267.2,20.78 267.32,20.91 268.72,20.91 268.97,21.16 269.28,21.16
TYPEC2_USB0 on TOP (solid shape): 266.05,26.27 266.05,25.22 265.84,25.01 265.84,24.07 266.06,23.85 266.06,23.14 266.01,23.1 262.87,23.1 262.59,23.37 262.59,26.24 262.76,26.4 265.91,26.4
TYPEC2_USB0 on BOTTOM (solid shape): 208.78,9 212.21,9 212.46,8.74 212.46,6.2 212.21,5.95 212.21,4.81 210.94,3.54 207.38,3.54 207.26,3.66 207.26,9.25 207.38,9.38 208.4,9.38
TYPEC2_USB0 on IN1 (solid shape): outline of 3501 points within 206.11,2.9 269.64,28.94
TYPEC2_USB0_R on BOTTOM (solid shape): 207,8.49 207,5.19 206.88,5.06 203.19,5.06 203.07,5.19 203.07,8.49 203.19,8.62 206.88,8.62
VCORE on TOP (solid shape): 191.26,47.71 191.26,42.29 189.66,40.69 187.72,40.69 186.91,41.49 185.24,41.49 184.4,42.33 184.4,43.65 184.63,43.88 185.44,43.88 185.57,44.01 185.57,44.86 185.49,44.94 185.49,44.95 184.37,44.95 183.92,45.41 183.92,47.79 184.07,47.95 191.03,47.95
VCORE on TOP (solid shape): outline of 1169 points within 116.87,38.53 135.94,50.94
VCORE on BOTTOM (solid shape): 191.08,45.66 191.08,39.67 190.76,39.35 185.5,39.35 182.44,42.41 182.44,44.03 181.38,45.09 181.15,45.32 181.15,46.18 181.2,46.24 190.5,46.24
VCORE on BOTTOM (solid shape): outline of 104 points within 116.81,38.49 136.98,52.26
VCORE on IN1 (solid shape): 191.26,45.94 191.26,42.29 189.66,40.69 187.72,40.69 186.91,41.49 186.91,41.49 186.91,47.23 187.62,47.95 189.26,47.95
VCORE on IN1 (solid shape): outline of 1112 points within 117.09,38.58 123.44,47.05
VCORE on GND1 (solid shape): outline of 238 points within 117.01,38.52 123.62,47.08
VCORE on IN2 (solid shape): 189.65,47.52 189.65,40.91 189.43,40.69 187.72,40.69 186.91,41.49 186.91,47.24 187.62,47.95 189.23,47.95
VCORE on IN2 (solid shape): outline of 1804 points within 117.08,38.59 135.94,52.75
VCORE on SVCC (solid shape): outline of 221 points within 117.01,38.53 190.55,59.97
VCORE on IN3 (solid shape): outline of 4718 points within 117.11,37.98 190.6,51.49
VCORE on GND2 (solid shape): outline of 173 points within 116.86,38.66 120.55,46.12
VCORE on IN4 (solid shape): 190.7,46.52 190.7,41.1 190.23,40.63 184.94,40.63 184.53,41.04 184.53,46.57 185.49,47.54 189.68,47.54
VCORE on IN4 (solid shape): outline of 624 points within 116.99,39.05 125.11,50.48
VGTA_BST1 on TOP (solid shape): 160.09,54.52 160.09,53.94 160.01,53.86 159.12,53.86 159.08,53.9 159.08,54.11 158.39,54.8 157.96,54.8 157.7,55.06 157.7,55.41 157.86,55.57 159.05,55.57
VOUTLDO on TOP (solid shape): 76.49,45.33 76.49,44.48 76.25,44.24 76.25,43.61 76.14,43.5 75.41,43.5 74.29,44.62 73.26,44.62 73.17,44.71 72.86,44.71 72.76,44.62 71.98,44.62 71.9,44.69 71.9,44.88 71.92,44.92 72.03,45.02 72.58,45.02 72.71,45.15 74.92,45.15 75.18,45.41 76.42,45.41
VSTBY_FSPI on TOP (solid shape): outline of 1320 points within 42.03,11.92 62.89,24.39
VSTBY_FSPI on BOTTOM (solid shape): 43.33,17.87 43.33,17.4 43.42,17.32 44.67,17.32 44.85,17.14 44.85,16.53 44.72,16.4 42.8,16.4 42.67,16.53 42.67,17.84 42.83,17.99 43.21,17.99
VSTBY_FSPI on IN3 (solid shape): 86.91,18.12 86.91,17.71 86.4,17.2 85.82,17.2 85.72,17.3 85.72,17.97 86.07,18.32 86.71,18.32
VSTBY_FSPI_R on BOTTOM (solid shape): 44.68,18.72 44.68,17.56 44.57,17.44 43.61,17.44 43.48,17.58 43.48,18.14 43.2,18.43 43.2,18.7 43.32,18.83 44.58,18.83
VSTBY_FSPI_R on BOTTOM (solid shape): 48.44,18.86 48.44,18.59 48.38,18.52 47.42,18.52 47.01,18.11 46.9,18.11 46.73,18.28 46.73,18.44 47.23,18.94 48.36,18.94
VSTBY_FSPI_R on BOTTOM (solid shape): 52.27,21.87 52.27,21.32 51.99,21.04 51.76,21.04 51.63,21.17 51.63,21.57 51.56,21.65 51.07,21.65 51.01,21.71 51.01,21.92 51.03,21.95 52.19,21.95
VSTBY_FSPI_R on BOTTOM (solid shape): 45.3,15.55 45.3,15.12 45.15,14.98 45.15,13.38 44.88,13.11 44.37,13.11 43.99,13.49 43.99,13.8 43.87,13.93 43.87,14.55 43.82,14.57 43.81,14.6 43.81,14.7 43.66,14.85 43.66,15.89 43.78,16.02 44.83,16.02
VSTBY_FSPI_R on IN1 (solid shape): outline of 643 points within 43.33,13.06 52.78,21.9
VSTBY_FSPI_R on IN3 (solid shape): outline of 176 points within 44.19,9.28 53.64,15.77
N18652907 on BOTTOM (solid shape): 61.59,42.79 61.59,41.67 61.49,41.57 60.04,41.57 59.84,41.77 59.84,42.97 60.03,43.16 61.21,43.16
N18652998 on BOTTOM (solid shape): 60.47,41.11 60.47,39.66 59.74,38.93 58.77,38.93 58.57,39.13 58.57,39.84 58.72,39.99 59.38,39.99 59.74,40.35 59.74,41.01 59.94,41.21 60.37,41.21
N18653022 on BOTTOM (solid shape): 81,43.04 81,42.33 80.87,42.2 78.99,42.2 78.89,42.31 78.89,42.92 79.12,43.14 80.89,43.14
N18653045 on BOTTOM (solid shape): 78.61,41.87 78.61,40.77 78.32,40.49 76.97,40.49 76.6,40.86 76.6,41.93 76.68,42 78.48,42
N18653149 on TOP (solid shape): 69.16,42.81 69.16,41.53 69.16,39.77 69.16,39.64 69.62,39.18 69.62,37.48 69.41,37.28 67.58,37.28 67.31,37.54 67.31,40.59 68.78,42.05 68.78,42.84 68.83,42.89 69.08,42.89
N18656165 on BOTTOM (solid shape): 74.49,54.55 74.49,52.77 74.39,52.67 73.04,52.67 72.82,52.89 72.66,52.89 72.49,53.07 72.49,53.55 72.57,53.64 73.03,53.64 73.48,54.08 73.48,54.52 73.71,54.75 74.29,54.75
N18656336 on BOTTOM (solid shape): 64.13,48.08 64.13,46.98 63.98,46.83 62.66,46.83 62.12,47.36 62.12,47.97 62.17,48.02 62.86,48.02 62.86,48.09 63.06,48.29 63.91,48.29
N18656394 on BOTTOM (solid shape): 76.8,54.9 76.8,54.13 76.51,53.84 75.95,53.84 75.56,53.45 75.56,53.2 75.33,52.97 75.08,52.97 74.8,53.25 74.8,54.85 75.08,55.13 76.57,55.13
N18664596 on BOTTOM (solid shape): 183.87,38.34 183.87,36.79 183.71,36.63 182.26,36.63 181.95,36.95 181.95,37.64 181.93,37.66 181.93,38.37 182.11,38.55 183.66,38.55
N18665779 on BOTTOM (solid shape): 174.42,38.37 174.42,36.84 174.19,36.61 172.74,36.61 172.49,36.86 172.49,38.39 172.59,38.5 174.29,38.5
N18668050 on BOTTOM (solid shape): 158.56,51.23 158.56,50.57 158.41,50.41 155.96,50.41 155.7,50.68 155.7,51.24 155.86,51.41 158.39,51.41
N19270898 on BOTTOM (solid shape): 209.17,25.5 209.17,24.75 208.81,24.39 208.81,23.89 208.52,23.6 208.52,22.76 208.41,22.65 206.79,22.65 206.67,22.77 206.67,23.99 207.3,24.62 207.3,24.69 207.3,24.69 207.3,25.46 207.39,25.55 209.12,25.55
N19975647 on BOTTOM (solid shape): 183.17,9.27 183.17,8.82 183.89,8.1 183.89,7.34 183.38,6.83 182.02,6.83 181.98,6.87 181.98,7.3 182.58,7.89 182.58,9.24 182.64,9.31 183.13,9.31
N19975767 on BOTTOM (solid shape): 199.93,33.19 199.93,32.05 199.85,31.97 198.54,31.97 198.07,31.5 196.59,31.5 196.57,31.52 196.57,32.04 196.6,32.07 197.82,32.07 198.27,32.52 199.14,32.52 199.31,32.69 199.31,33.22 199.45,33.36 199.76,33.36
N19975775 on BOTTOM (solid shape): 201.84,32.13 201.84,31.53 201.82,31.51 200.73,31.51 200.48,31.26 200.48,30.23 200.43,30.18 200.07,30.18 200.03,30.22 200.03,30.57 199.36,31.24 199.36,31.67 199.43,31.74 199.94,31.74 200.36,32.16 201.81,32.16
N20614892 on BOTTOM (solid shape): 238.42,2.94 239.55,2.94 239.64,3.03 240.16,3.03 240.33,2.86 240.33,2.12 240.25,2.05 237.41,2.05 237.31,2.15 237.31,3.06 237.36,3.11 238.25,3.11
N20690993 on BOTTOM (solid shape): 79.24,26.36 79.24,25.14 79.06,24.96 77.41,24.96 77.31,25.06 77.31,25.89 78.15,26.73 78.87,26.73
N20691132 on BOTTOM (solid shape): 80.36,15.84 80.36,14.79 80.26,14.79 80.26,14.6 80,14.34 78.81,14.34 78.46,14.7 78.46,15.92 78.66,16.12 80.08,16.12
N22912068 on BOTTOM (solid shape): 53.11,41.18 53.11,40.44 53,40.34 51,40.34 50.92,40.42 50.92,41.13 51.1,41.31 52.98,41.31
N22925492 on BOTTOM (solid shape): 57.12,40.01 57.12,38.84 56.89,38.62 54.98,38.62 54.76,38.84 54.76,40.01 54.96,40.22 56.92,40.22
N22926183 on BOTTOM (solid shape): 164.89,29.29 164.89,28.02 164.89,28.01 164.89,27.65 164.62,27.39 164.61,27.38 164.55,27.34 164.51,27.28 164.51,27.27 163.98,26.74 163.55,26.74 163.45,26.84 163.45,27.14 163.86,27.55 164.07,27.55 164.07,28.18 163.9,28.18 163.74,28.34 163.74,29.35 163.88,29.49 164.69,29.49
N22926200 on BOTTOM (solid shape): 164.91,31.62 164.91,29.93 164.82,29.84 164.13,29.84 164.03,29.94 164.03,31.61 164.19,31.77 164.77,31.77
N23037532 on TOP (solid shape): 43.62,57.01 43.62,56.27 43.76,56.12 44.76,56.12 44.93,55.96 44.93,54.35 44.38,53.8 43.85,53.8 41.52,51.48 41.52,50.71 41.4,50.58 40.68,50.58 40.63,50.63 40.63,52.94 41.3,53.61 42.19,53.61 42.34,53.76 42.34,54.46 42.34,54.46 42.53,54.65 43.14,54.65 43.27,54.79 43.27,55.36 43.12,55.52 43.12,56.5 43.13,56.5 43.13,56.98 43.25,57.1 43.53,57.1
N25078926 on BOTTOM (solid shape): 211.92,12.22 211.92,10.7 211.27,10.05 211.27,9.44 211.2,9.36 209.5,9.36 209.47,9.4 209.47,10.71 210.12,11.36 210.12,12.11 210.23,12.23 211.91,12.23
N25079793 on BOTTOM (solid shape): 202.63,12.55 202.84,12.55 202.99,12.4 202.99,12.1 202.87,11.97 202.58,11.97 202.33,12.22 202.24,12.22 202.24,12.26 201.61,12.26 201.61,12.22 199.14,12.22 199.12,12.24 199.12,12.77 199.22,12.87 202.31,12.87
N25079814 on BOTTOM (solid shape): 202.61,11.31 203.81,11.31 203.9,11.22 203.9,10.13 203.38,9.61 199.42,9.61 199.1,9.92 199.1,10.81 199.18,10.89 200.41,10.89 200.57,10.73 200.57,10.43 200.67,10.33 201.47,10.33 201.68,10.54 202.27,10.54 202.33,10.61 202.33,11.18 202.47,11.31 202.61,11.31
N262237880 on BOTTOM (solid shape): 59.51,48.39 59.51,46.54 59.13,46.16 58.54,46.16 58.3,46.4 58.3,46.88 57.73,47.45 57.73,48.57 57.83,48.67 59.23,48.67

Small or netless copper shapes (teardrops, artwork), in the pictures only: 57 on TOP, 38 on BOTTOM, 7 on IN1, 20 on GND1, 8 on IN2, 28 on IN3, 1 on GND2, 6 on IN4

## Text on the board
Ref Des/Silkscreen Bottom: DA0ZDSMBAF0 REV:F | MODEL:ZDS
User.Comments: 31.0x37.0 | PARTITION_2 | PARTITION_3
Ref Des/Silkscreen Top: DA0ZDSMBAF0 REV:F
User.12: GND | V4_VCCIO | +VIN | V11_V1.00A | VCCSA | VCORE | +3V | +TYPEC_VBUS_C | ADOGND | V6_V3.3A_DSW | +WL_VDD
User.28: GND | ADOGND
User.45: FIGURE | TYPE | Circle | SIZE | 4.0 | DRILL CHART: TOP to IN1 | ALL UNITS ARE IN MILS | DRILL CHART: IN1 to GND1 | PLATED | ROTATION | - | QTY | 1408 | 1078 | 8.0 | DRILL CHART: GND1 to IN2 | DRILL CHART: GND1 to GND2 | 446 | 572 | DRILL CHART: IN3 to GND2 | DRILL CHART: GND2 to IN4 | 372 | 1297 | Oblong | 10.0 | 14.0 | 16.0 | 20.0 | 98.0 | 110.0 | 177.0 | 197.0 | 28.0 | 31.0 | 35.0 | 43.0 | 51.0 | 63.0 | 79.0 | 55.0x20.0 | 57.0x24.0 | 63.0x24.0 | 69.0x20.0 | 118.0x79.0 | DRILL CHART: IN4 to BOTTOM | DRILL CHART: TOP to BOTTOM | NON-PLATED | 0.000 | 90.000 | 1431 | 1754 | 19 | 580 | 24 | 68 | 4 | 2 | 1 | 2468 | 6 | 21 | TOTAL HOLES:
